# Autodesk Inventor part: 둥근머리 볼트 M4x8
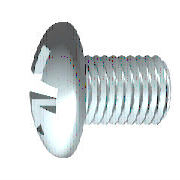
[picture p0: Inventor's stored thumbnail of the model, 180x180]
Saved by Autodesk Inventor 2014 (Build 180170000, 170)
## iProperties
Created: 2012-02
Part Number: 둥근머리 볼트 M4x8
Material: 강철, 연강
Description: 십자 오목 머리 나사
Document SubType Name: Modeling
Standard: KS B 1023
Designer: mduedu
Standards Organization: KS
Language: ko-KR
Size Designation: A  M 4 x 8 - H
Categories: <MemberInstance><Categories><Category DisplayName="조임쇠" InternalName="e4da775c-781d-43d5-af7c-5136215cf5a6" Mnemonic="FSTN"><Category DisplayName="볼트" InternalN
Density: 7.86 g/cm^3
Appearance: 노란색
Mass: 1.6193 g
Surface Area: 2.62078 cm^2
Volume: 0.206017 cm^3
IsCustomPart: 1
Author: mduedu
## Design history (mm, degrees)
body "Solid1"
workplane "Work Plane3"
sketch "스케치2"
  geometry: L1 (-5.374, 0)-(5.374, 0) reference; L2 (0, -5.374)-(0, 5.374) reference; L3 (0, 2.3)-(0, 0); L4 (0, 0)-(2.3, 0); L5 (0, 0)-(2.714, 2.714); L6 (0.311, 2.279)-(0.392, 0.703); L7 (2.279, 0.311)-(0.703, 0.392); L8 (0.311, -2.279)-(0.392, -0.703); L9 (2.279, -0.311)-(0.703, -0.392); L10 (-0.311, 2.279)-(-0.392, 0.703); L11 (-2.279, 0.311)-(-0.703, 0.392); L12 (-2.279, -0.311)-(-0.703, -0.392); L13 (-0.311, -2.279)-(-0.392, -0.703); A1 r 0.69 centre (0, 0) between (0.69, 0) and (0, 0.69); A2 r 2.3 centre (0, 0) between (2.3, 0) and (2.279, 0.311); A3 r 2.3 centre (0, 0) between (0.311, 2.279) and (0, 2.3); A4 r 2.3 centre (0, 0) between (2.279, 0.311) and (0.311, 2.279); A5 r 2.3 centre (0, 0) between (0, -2.3) and (0.311, -2.279); A6 r 2.3 centre (0, 0) between (0.311, -2.279) and (2.279, -0.311); A7 r 2.3 centre (0, 0) between (2.279, -0.311) and (2.3, 0); A8 r 2.3 centre (0, 0) between (-2.279, 0.311) and (-2.3, 0); A9 r 2.3 centre (0, 0) between (-0.311, 2.279) and (-2.279, 0.311); A10 r 2.3 centre (0, 0) between (0, 2.3) and (-0.311, 2.279); A11 r 2.3 centre (0, 0) between (-2.3, 0) and (-2.279, -0.311); A12 r 2.3 centre (0, 0) between (-2.279, -0.311) and (-0.311, -2.279); A13 r 2.3 centre (0, 0) between (-0.311, -2.279) and (0, -2.3); A14 r 0.805 centre (0, 0) between (0.805, 0) and (0, 0.805); A15 r 0.328 centre (0.72, 0.72) between (0.392, 0.703) and (0.703, 0.392); A16 r 0.328 centre (0.72, -0.72) between (0.703, -0.392) and (0.392, -0.703); A17 r 0.328 centre (-0.72, 0.72) between (-0.703, 0.392) and (-0.392, 0.703); A18 r 0.328 centre (-0.72, -0.72) between (-0.392, -0.703) and (-0.703, -0.392); 1 further point
  constraints: 38 point on circle, 22 end point, 19 symmetric about line, 18 centre point, 4 coincident, 3 collinear, 3 point on line, 3 tangent, 1 perpendicular, 21 other
  dimensions: "d4" = 45 deg angle of L5 L4; "d5" = 1.38 diameter of A1 (= 0.3 x SDM); "d6" = 4.6 diameter of A4 (= SDM); "d7" = 0.3115 distance from line of L6.start L3 (= 0.5 x SBR); "d14" = 1.61 diameter of A14 (= 0.35 x SDM)
extrude "슬롯" join sketch "스케치2" taper "d15" = 5 deg; stored distance "d54" = 10
revolve "절단부" stored, may be unused: angle "d56" = 90 deg
revolve "본체" stored, may be unused: angle "d18" = 90 deg
workplane "Work Plane1"
sketch "스케치1"
  geometry: L1 (8, 0)-(8, 2); L2 (8, 2)-(1.4, 2); L3 (3.962, 5.08)-(3.962, 5.08); L4 (-3.1, 0)-(-3.1, 3.729); L5 (-2.744, 2.122)-(-1.498, 1.501); L6 (-1.498, 1.501)-(-0.7, 0); L7 (-0.7, 0)-(8, 0); L8 (-5.687, 0)-(10.281, 0) reference; L9 (0, -1.016)-(0, 6.096) reference; L10 (-2.744, 2.122)-(-3.1, 2.3); L11 (-1.846, 3.839)-(-3.1, 3.729); L12 (-1.846, 3.839)-(0, 4); L13 (0, 4)-(0, 1.785); L14 (0, 1.785)-(0.971, 1.785); L15 (0.971, 1.785)-(1.4, 2); L16 (1.4, 2)-(0, 2); A1 r 6.5 centre (3.4, 0) between (-1.846, 3.839) and (-3.1, 0)
  constraints: 28 end point, 5 point on line, 4 collinear, 4 point on circle, 3 parallel, 2 perpendicular, 1 centre point, 1 horizontal, 1 tangent
  dimensions: "d1" = 4 diameter of L2 L7 (= GD); "d2" = 2.4 distance from line of L6.end L4 (= STI); "d11" = 4.6 diameter of L10.end L7 (= SDM); "d12" = 62 deg angle of L6 L7; "d13" = 26.5 deg angle of L5 L7; "d17" = 8 diameter of L12.end L7 (= KOD); "d19" = 5 deg angle of L12 L7 (= KEWI); "d20" = 3.1 distance between parallel lines of L4 L13 (= KOH); "d21" = 6.5 radius of A1 (= KR); "d23" = 3.5705 diameter of L14 L7 (= BDM); "d24" = 6.6 distance of L1.end L2.end (= GEL); "d25" = 0.42941 horizontal distance of L14.end L2.end (= GAL); "d28" = 8 distance between parallel lines of L1 L13 (= NLG)
fillet "모깎기1" dims "d29" = 1.6 (= RR)
fillet "모깎기2" dims "d16" = 0.1246 (= 0.2 x SBR)
feature "스레드" dims "d8" = 6.6 (= GEL), "d9" = 0
chamfer "모따기1" distance "d26" = 0.42941 (= -0.5 x SPD + 0.5 x GD); stored, may be unused: second distance "d27" = 0.42952 (computed from GUL), angle "d78" = 45 deg
other parameters: "GD" = 4 (= NND) [user parameter; used in 2 equation terms], "NLG" = 8 [user parameter; used in 1 equation term], "GEL" = 6.6 [user parameter; used in 2 equation terms], "KOD" = 8 [user parameter; used in 1 equation term], "KOH" = 3.1 [user parameter; used in 2 equation terms], "SDM" = 4.6 [user parameter; used in 4 equation terms], "STI" = 2.4 [user parameter; used in 1 equation term], "SBR" = 0.623 [user parameter; used in 2 equation terms], "GAL" = 0.42941 (= 0.61345 x PTC) [user parameter; used in 1 equation term], "SPD" = 3.14117 (= NND - 1.2269 x PTC) [user parameter; used in 1 equation term], "KEWI" = 5 deg [user parameter; used in 1 equation term], "d3" = -3.1 (= -KOH), "d10" = 0, "KR" = 6.5 [user parameter; used in 1 equation term], "BDM" = 3.5705 [user parameter; used in 1 equation term], "GUL" = 0.42941 (= 0.61345 x PTC) [user parameter; used in 1 equation term], "RR" = 1.6 [user parameter; used in 1 equation term], "d79" = 0, "d80" = 0, "PTC" = 0.7 [user parameter; used in 5 equation terms], "THREADDIA" = 4 [user parameter; used in 1 equation term], "TOA" = 30 deg [user parameter], "TPU" = 14.28571 (computed from PTC) [user parameter], "NND" = 4 [user parameter; used in 2 equation terms], "GD1" = 3.14117 (= THREADDIA - 1.2269 x PTC) [user parameter]
